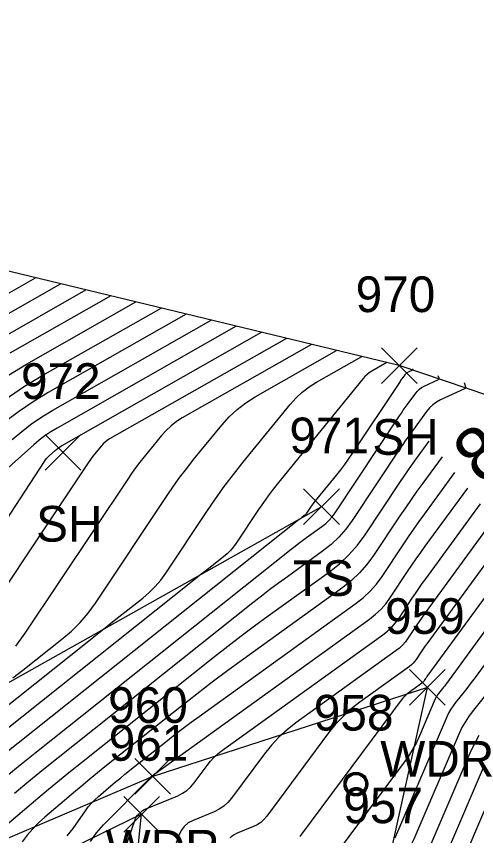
# Model space of a CAD drawing. Extents: x 1650836 to 1652450, y 332578 to 333908.
# Drawn here: x 1652020.77 to 1652046.56, y 332883.74 to 332929.66 of the extents above; entities that cross this region are included whole.
import ezdxf

# ---------------------------------------------------------------- set-up
doc = ezdxf.new("R2010")
doc.units = 0
for name, color, linetype in [('L_A', 7, 'Continuous'), ('L_I', 7, 'Continuous'), ('L_TIC', 7, 'Continuous'), ('LAWA', 7, 'Continuous'), ('LELB', 7, 'Continuous'), ('LSOGCMA', 7, 'Continuous'), ('LSOGCMA_T', 7, 'Continuous'), ('LSOGCMI', 7, 'Continuous'), ('LSOGP', 7, 'Continuous'), ('R_I', 7, 'Continuous'), ('R_TIC', 7, 'Continuous'), ('RDW', 7, 'Continuous'), ('U_I', 7, 'Continuous'), ('UWW', 7, 'Continuous')]:
    doc.layers.add(name, color=color, linetype=linetype)

msp = doc.modelspace()

# ---------------------------------------------------------------- linework, layer by layer
at = {"layer": 'L_TIC'}
for points in [[(1652041.229, 332909.088), (1652043.229, 332911.088)], [(1652043.229, 332909.088), (1652041.229, 332911.088)], [(1652022.391, 332904.221), (1652024.391, 332906.221)], [(1652024.391, 332904.221), (1652022.391, 332906.221)], [(1652036.868, 332901.175), (1652038.868, 332903.175)], [(1652038.868, 332901.175), (1652036.868, 332903.175)], [(1652042.799, 332891.048), (1652044.799, 332893.048)], [(1652044.799, 332891.048), (1652042.799, 332893.048)], [(1652027.411, 332886.059), (1652029.411, 332888.059)], [(1652029.411, 332886.059), (1652027.411, 332888.059)]]:
    msp.add_lwpolyline(points, dxfattribs=at)
at = {"layer": 'LAWA'}
msp.add_lwpolyline([(1652029.035, 332873.993), (1652029.332, 332877.691), (1652041.456, 332881.438), (1652043.799, 332892.048), (1652028.411, 332887.059), (1652010.628, 332879.467), (1652005.763, 332881.337), (1651975.403, 332896.414), (1651937.407, 332919.099), (1651902.904, 332934.281), (1651873.829, 332953.989)], dxfattribs=at)
at = {"layer": 'LELB'}
msp.add_lwpolyline([(1652037.868, 332902.175), (1652009.704, 332886.341)], dxfattribs=at)
at = {"layer": 'LSOGCMA'}
for points in [[(1651982.104, 332899.542), (1652000.106, 332897.594), (1652000.186, 332897.593), (1652000.261, 332897.606), (1652000.331, 332897.635), (1652000.398, 332897.678), (1652000.655, 332897.882), (1652000.718, 332897.933), (1652000.782, 332897.986), (1652000.844, 332898.039), (1652000.905, 332898.093), (1652015.035, 332910.743), (1652015.649, 332911.264), (1652016.288, 332911.75), (1652016.952, 332912.201), (1652017.641, 332912.618), (1652021.85, 332915.012)], [(1652035.907, 332911.616), (1652025.987, 332905.974), (1652025.861, 332905.894), (1652025.743, 332905.803), (1652025.635, 332905.703), (1652025.535, 332905.591), (1652025.155, 332905.124), (1652025.062, 332905.006), (1652024.971, 332904.886), (1652024.883, 332904.764), (1652024.798, 332904.639), (1652016.954, 332892.876)], [(1652023.627, 332883.722), (1652023.793, 332883.93), (1652023.95, 332884.145), (1652024.638, 332885.134), (1652024.8, 332885.352), (1652024.976, 332885.557), (1652025.164, 332885.751), (1652025.366, 332885.933), (1652026.199, 332886.638), (1652026.407, 332886.813), (1652026.617, 332886.987), (1652026.829, 332887.159), (1652027.041, 332887.33), (1652029.235, 332889.077), (1652029.674, 332889.422), (1652030.117, 332889.762), (1652030.564, 332890.096), (1652031.014, 332890.425), (1652039.81, 332896.764), (1652040.224, 332897.091), (1652040.604, 332897.452), (1652040.95, 332897.845), (1652041.261, 332898.272), (1652042.438, 332900.043), (1652042.734, 332900.485), (1652043.036, 332900.923), (1652043.342, 332901.357), (1652043.653, 332901.788), (1652045.34, 332904.096)], [(1652046.933, 332887.542), (1652044.985, 332882.999), (1652044.53, 332882.085), (1652043.981, 332881.242), (1652043.336, 332880.469), (1652042.596, 332879.767), (1652041.021, 332878.432)]]:
    msp.add_lwpolyline(points, dxfattribs=at)
at = {"layer": 'LSOGCMI'}
for points in [[(1652023.256, 332914.673), (1652018.565, 332912.004)], [(1652019.49, 332911.391), (1652024.662, 332914.333)], [(1652026.067, 332913.993), (1652020.414, 332910.778)], [(1652020.334, 332909.557), (1652021.338, 332910.164), (1652027.473, 332913.654)], [(1652030.284, 332912.974), (1652022.56, 332908.581), (1652021.706, 332908.065), (1652020.883, 332907.505), (1652020.092, 332906.903)], [(1652020.136, 332908.187), (1652021.18, 332908.896), (1652022.263, 332909.551), (1652028.878, 332913.314)], [(1652020.538, 332905.95), (1652021.072, 332906.403), (1652021.629, 332906.826), (1652022.207, 332907.219), (1652022.807, 332907.582), (1652031.69, 332912.635)], [(1652033.095, 332912.295), (1652023.054, 332906.583), (1652022.708, 332906.374), (1652022.374, 332906.147), (1652022.053, 332905.903), (1652021.745, 332905.642), (1652020.537, 332904.56), (1652020.245, 332904.281), (1652019.973, 332903.985), (1652019.721, 332903.671), (1652019.49, 332903.34), (1652012.737, 332892.984), (1652012.351, 332892.446), (1652011.92, 332891.948), (1652011.446, 332891.493), (1652010.928, 332891.079), (1652008.546, 332889.342), (1652008.106, 332889.06), (1652007.844, 332888.935)], [(1652007.881, 332887.532), (1652008.025, 332887.56), (1652008.577, 332887.743), (1652009.101, 332887.993), (1652009.598, 332888.312), (1652012.291, 332890.275), (1652012.877, 332890.743), (1652013.413, 332891.258), (1652013.899, 332891.82), (1652014.336, 332892.429), (1652022.35, 332904.72), (1652022.412, 332904.808), (1652022.479, 332904.892), (1652022.552, 332904.971), (1652022.63, 332905.045), (1652022.952, 332905.333), (1652023.034, 332905.403), (1652023.12, 332905.468), (1652023.208, 332905.529), (1652023.301, 332905.585), (1652034.501, 332911.956)], [(1652037.312, 332911.276), (1652030.068, 332907.156), (1652029.743, 332906.95), (1652029.441, 332906.718), (1652029.162, 332906.459), (1652028.906, 332906.172), (1652027.929, 332904.97), (1652027.688, 332904.667), (1652027.455, 332904.358), (1652027.229, 332904.044), (1652027.011, 332903.725), (1652021.255, 332895.094), (1652020.72, 332894.356)], [(1652020.581, 332892.58), (1652021.13, 332893.013), (1652023.325, 332894.745), (1652023.854, 332895.197), (1652024.342, 332895.686), (1652024.79, 332896.212), (1652025.198, 332896.775), (1652029.223, 332902.81), (1652029.575, 332903.325), (1652029.939, 332903.831), (1652030.315, 332904.328), (1652030.703, 332904.816), (1652032.277, 332906.753), (1652032.689, 332907.215), (1652033.138, 332907.633), (1652033.625, 332908.007), (1652034.148, 332908.337), (1652038.718, 332910.937)], [(1652015.744, 332887.432), (1652024.83, 332894.668), (1652025.207, 332894.968), (1652025.584, 332895.267), (1652025.961, 332895.566), (1652026.339, 332895.865), (1652027.851, 332897.058), (1652028.215, 332897.369), (1652028.552, 332897.705), (1652028.86, 332898.068), (1652029.141, 332898.455), (1652031.445, 332901.909), (1652031.926, 332902.612), (1652032.423, 332903.304), (1652032.936, 332903.983), (1652033.466, 332904.65), (1652036.118, 332907.912), (1652036.44, 332908.273), (1652036.791, 332908.6), (1652037.171, 332908.892), (1652037.581, 332909.151), (1652040.124, 332910.597)], [(1652041.529, 332910.258), (1652040.684, 332909.777), (1652040.548, 332909.691), (1652040.422, 332909.594), (1652040.305, 332909.485), (1652040.198, 332909.365), (1652035.455, 332903.532), (1652035.165, 332903.166), (1652034.883, 332902.794), (1652034.611, 332902.415), (1652034.347, 332902.029), (1652033.085, 332900.136), (1652032.93, 332899.923), (1652032.761, 332899.725), (1652032.577, 332899.54), (1652032.377, 332899.37), (1652031.549, 332898.716), (1652031.341, 332898.552), (1652031.135, 332898.389), (1652030.928, 332898.225), (1652030.721, 332898.06), (1652017.856, 332887.814)], [(1652042.959, 332909.899), (1652042.974, 332909.851), (1652042.975, 332909.843), (1652042.974, 332909.837), (1652042.97, 332909.832), (1652042.964, 332909.828), (1652042.693, 332909.702), (1652042.647, 332909.677), (1652042.606, 332909.647), (1652042.569, 332909.612), (1652042.536, 332909.572), (1652042.376, 332909.354), (1652042.339, 332909.303), (1652042.303, 332909.252), (1652042.267, 332909.2), (1652042.232, 332909.148), (1652039.567, 332905.135), (1652039.363, 332904.836), (1652039.153, 332904.542), (1652038.935, 332904.254), (1652038.71, 332903.97), (1652037.444, 332902.413), (1652037.393, 332902.349), (1652037.344, 332902.283), (1652037.296, 332902.217), (1652037.249, 332902.149), (1652037.028, 332901.817), (1652037.001, 332901.779), (1652036.971, 332901.745), (1652036.939, 332901.712), (1652036.903, 332901.682), (1652036.758, 332901.567), (1652036.722, 332901.539), (1652036.685, 332901.51), (1652036.649, 332901.481), (1652036.613, 332901.452), (1652019.967, 332888.196)], [(1652019.767, 332886.712), (1652020.786, 332887.542), (1652021.811, 332888.364), (1652036.173, 332899.802), (1652036.384, 332899.968), (1652036.596, 332900.131), (1652036.81, 332900.291), (1652037.026, 332900.449), (1652037.895, 332901.075), (1652038.103, 332901.239), (1652038.294, 332901.421), (1652038.468, 332901.619), (1652038.625, 332901.833), (1652042.239, 332907.276), (1652042.344, 332907.431), (1652042.45, 332907.586), (1652042.558, 332907.739), (1652042.668, 332907.891), (1652043.146, 332908.545), (1652043.245, 332908.664), (1652043.356, 332908.769), (1652043.48, 332908.858), (1652043.617, 332908.932), (1652044.426, 332909.309), (1652044.445, 332909.321), (1652044.457, 332909.337), (1652044.461, 332909.356), (1652044.457, 332909.378), (1652044.413, 332909.522)], [(1652045.868, 332909.145), (1652045.941, 332908.905), (1652045.947, 332908.868), (1652045.94, 332908.836), (1652045.921, 332908.81), (1652045.889, 332908.79), (1652044.54, 332908.161), (1652044.313, 332908.038), (1652044.107, 332907.89), (1652043.921, 332907.716), (1652043.756, 332907.517), (1652042.96, 332906.428), (1652042.777, 332906.174), (1652042.597, 332905.919), (1652042.42, 332905.662), (1652042.246, 332905.403), (1652039.587, 332901.399), (1652039.231, 332900.912), (1652038.836, 332900.462), (1652038.402, 332900.051), (1652037.929, 332899.677), (1652035.957, 332898.256), (1652035.466, 332897.897), (1652034.98, 332897.533), (1652034.498, 332897.164), (1652034.021, 332896.788), (1652023.118, 332888.105), (1652022.297, 332887.446), (1652021.48, 332886.781), (1652020.668, 332886.109)], [(1652018.845, 332883.187), (1652021.973, 332885.834), (1652022.581, 332886.344), (1652023.192, 332886.849), (1652023.807, 332887.35), (1652024.426, 332887.847), (1652031.868, 332893.773), (1652032.612, 332894.359), (1652033.364, 332894.936), (1652034.123, 332895.504), (1652034.888, 332896.062), (1652038.315, 332898.532), (1652038.884, 332898.982), (1652039.406, 332899.477), (1652039.882, 332900.018), (1652040.31, 332900.605), (1652042.253, 332903.53), (1652042.497, 332903.893), (1652042.744, 332904.253), (1652042.996, 332904.61), (1652043.252, 332904.964), (1652043.901, 332905.852)], [(1652044.62, 332904.974), (1652043.544, 332903.501), (1652043.215, 332903.046), (1652042.892, 332902.587), (1652042.573, 332902.124), (1652042.26, 332901.658), (1652040.785, 332899.438), (1652040.416, 332898.932), (1652040.005, 332898.465), (1652039.554, 332898.037), (1652039.062, 332897.648), (1652033.5, 332893.639), (1652032.619, 332892.996), (1652031.745, 332892.342), (1652030.88, 332891.678), (1652030.022, 332891.004), (1652025.734, 332887.588), (1652025.318, 332887.255), (1652024.905, 332886.918), (1652024.494, 332886.578), (1652024.086, 332886.236), (1652022.367, 332884.782), (1652022.017, 332884.466), (1652021.69, 332884.129), (1652021.385, 332883.771), (1652021.104, 332883.393)], [(1652024.919, 332883.414), (1652025.257, 332883.895), (1652025.653, 332884.34), (1652028.178, 332886.889), (1652028.186, 332886.899), (1652028.195, 332886.908), (1652028.203, 332886.918), (1652028.21, 332886.929), (1652028.241, 332886.972), (1652028.248, 332886.982), (1652028.256, 332886.991), (1652028.264, 332887), (1652028.273, 332887.008), (1652028.311, 332887.04), (1652028.32, 332887.048), (1652028.33, 332887.056), (1652028.34, 332887.064), (1652028.349, 332887.071), (1652028.448, 332887.15), (1652028.468, 332887.166), (1652028.488, 332887.181), (1652028.508, 332887.196), (1652028.529, 332887.211), (1652040.558, 332895.88), (1652040.894, 332896.146), (1652041.203, 332896.439), (1652041.484, 332896.759), (1652041.737, 332897.105), (1652042.693, 332898.545), (1652042.934, 332898.903), (1652043.179, 332899.259), (1652043.428, 332899.612), (1652043.681, 332899.962), (1652046.059, 332903.218)], [(1652025.199, 332878.188), (1652027.422, 332884.647), (1652027.448, 332884.711), (1652027.481, 332884.771), (1652027.52, 332884.827), (1652027.566, 332884.879), (1652027.763, 332885.078), (1652027.815, 332885.125), (1652027.87, 332885.166), (1652027.929, 332885.201), (1652027.991, 332885.23), (1652029.814, 332885.98), (1652030.083, 332886.112), (1652030.327, 332886.276), (1652030.546, 332886.472), (1652030.74, 332886.701), (1652031.467, 332887.679), (1652031.656, 332887.915), (1652031.863, 332888.134), (1652032.085, 332888.337), (1652032.324, 332888.524), (1652041.305, 332894.996), (1652041.564, 332895.201), (1652041.802, 332895.426), (1652042.018, 332895.672), (1652042.212, 332895.939), (1652042.948, 332897.046), (1652043.133, 332897.322), (1652043.322, 332897.596), (1652043.513, 332897.867), (1652043.708, 332898.137), (1652046.779, 332902.34)], [(1652047.418, 332901.351), (1652043.735, 332896.311), (1652043.599, 332896.123), (1652043.465, 332895.932), (1652043.333, 332895.741), (1652043.203, 332895.548), (1652042.688, 332894.772), (1652042.552, 332894.585), (1652042.401, 332894.413), (1652042.234, 332894.255), (1652042.053, 332894.112), (1652036.431, 332890.061), (1652035.942, 332889.679), (1652035.486, 332889.263), (1652035.063, 332888.813), (1652034.674, 332888.329), (1652032.822, 332885.835), (1652032.618, 332885.596), (1652032.389, 332885.39), (1652032.133, 332885.218), (1652031.851, 332885.08), (1652030.67, 332884.594), (1652030.398, 332884.45), (1652030.174, 332884.261), (1652029.997, 332884.028), (1652029.867, 332883.749), (1652029.066, 332881.486)], [(1652048.028, 332900.324), (1652043.763, 332894.486), (1652043.685, 332894.378), (1652043.608, 332894.269), (1652043.532, 332894.159), (1652043.458, 332894.049), (1652043.164, 332893.606), (1652043.086, 332893.499), (1652042.999, 332893.4), (1652042.904, 332893.31), (1652042.801, 332893.228), (1652040.009, 332891.217), (1652039.525, 332890.839), (1652039.074, 332890.427), (1652038.655, 332889.982), (1652038.27, 332889.503), (1652034.799, 332884.828), (1652034.642, 332884.644), (1652034.465, 332884.485), (1652034.267, 332884.352), (1652034.05, 332884.246), (1652033.139, 332883.871), (1652032.93, 332883.76), (1652032.757, 332883.615)], [(1652036.665, 332883.692), (1652036.776, 332883.822), (1652042.411, 332891.409), (1652042.507, 332891.529), (1652042.612, 332891.641), (1652042.726, 332891.744), (1652042.847, 332891.839), (1652043.548, 332892.344), (1652043.574, 332892.365), (1652043.598, 332892.388), (1652043.62, 332892.412), (1652043.639, 332892.439), (1652043.713, 332892.55), (1652043.732, 332892.578), (1652043.751, 332892.606), (1652043.77, 332892.633), (1652043.79, 332892.66), (1652048.638, 332899.296)], [(1652049.249, 332898.269), (1652044.865, 332892.269), (1652044.812, 332892.198), (1652044.759, 332892.127), (1652044.704, 332892.056), (1652044.649, 332891.986), (1652044.427, 332891.708), (1652044.374, 332891.637), (1652044.326, 332891.563), (1652044.283, 332891.486), (1652044.246, 332891.406), (1652043.353, 332889.326), (1652043.183, 332888.958), (1652042.992, 332888.602), (1652042.78, 332888.257), (1652042.547, 332887.925), (1652038.752, 332882.815)], [(1652050.104, 332897.577), (1652046.469, 332892.602), (1652046.337, 332892.423), (1652046.203, 332892.245), (1652046.066, 332892.069), (1652045.928, 332891.894), (1652045.371, 332891.198), (1652045.239, 332891.02), (1652045.119, 332890.834), (1652045.012, 332890.641), (1652044.917, 332890.44), (1652042.075, 332883.813), (1652041.971, 332883.589)], [(1652047.207, 332891.801), (1652046.316, 332890.687), (1652046.104, 332890.402), (1652045.912, 332890.105), (1652045.74, 332889.795), (1652045.589, 332889.474), (1652043.049, 332883.55), (1652042.523, 332882.494), (1652041.888, 332881.52), (1652041.143, 332880.626), (1652040.288, 332879.814), (1652038.89, 332878.63)], [(1652039.955, 332878.531), (1652041.442, 332879.791), (1652042.24, 332880.548), (1652042.934, 332881.381), (1652043.527, 332882.29), (1652044.017, 332883.274), (1652046.261, 332888.508), (1652046.469, 332888.95), (1652046.705, 332889.376)], [(1652047.605, 332886.576), (1652045.953, 332882.723), (1652045.534, 332881.881), (1652045.027, 332881.103), (1652044.433, 332880.391), (1652043.751, 332879.743), (1652041.813, 332878.101)]]:
    msp.add_lwpolyline(points, dxfattribs=at)
at = {"layer": 'LSOGP'}
msp.add_lwpolyline([(1652322.392, 332778.396), (1652286.244, 332816.269), (1652278.684, 332833.467), (1652279.741, 332838.109), (1652281.376, 332840.252), (1652284.715, 332848.326), (1652266.979, 332860.629), (1652252.966, 332867.026), (1652234.442, 332886.186), (1652219.944, 332895.981), (1652193.017, 332893.494), (1652163.094, 332891.822), (1652141.158, 332895.272), (1652101.604, 332894.697), (1652074.965, 332899.016), (1652042.229, 332910.088), (1652009.557, 332917.982), (1651992.258, 332920.35), (1651945.495, 332936.417)], dxfattribs=at)
at = {"layer": 'R_TIC'}
for points in [[(1652026.792, 332883.937), (1652028.792, 332885.937)], [(1652028.792, 332883.937), (1652026.792, 332885.937)]]:
    msp.add_lwpolyline(points, dxfattribs=at)
at = {"layer": 'RDW'}
msp.add_lwpolyline([(1652007.153, 332861.07), (1652010.739, 332865.279), (1652018.452, 332871.644), (1652026.901, 332876.261), (1652027.792, 332884.937), (1652012.255, 332877.382), (1652007.989, 332873.849), (1651997.288, 332866.232)], dxfattribs=at)
at = {"layer": 'UWW'}
for radius in [0.667, 0.625, 0.583, 0.542]:
    msp.add_circle((1652039.799, 332886.631), radius, dxfattribs=at)

# ---------------------------------------------------------------- texts
at = {"layer": 'L_A'}
for s, p in [('SH', (1652040.717, 332905.088)), ('SH', (1652021.879, 332900.221)), ('TS', (1652036.277, 332897.175)), ('WDR', (1652041.161, 332887.048)), ('WDR', (1652025.773, 332882.059))]:
    msp.add_text(s, height=2, dxfattribs=at).set_placement(p)
at = {"layer": 'L_I'}
for s, p in [('970', (1652039.78, 332913.088)), ('972', (1652021.029, 332908.221)), ('971', (1652036.072, 332905.175)), ('959', (1652041.429, 332895.048)), ('960', (1652025.915, 332890.059)), ('957', (1652039.094, 332884.438))]:
    msp.add_text(s, height=2, dxfattribs=at).set_placement(p)
at = {"layer": 'LSOGCMA_T'}
msp.add_text('815', height=3, rotation=39.3343, dxfattribs=at).set_placement((1652046.855, 332903.309))
at = {"layer": 'R_I'}
msp.add_text('961', height=2, dxfattribs=at).set_placement((1652025.949, 332887.937))
at = {"layer": 'U_I'}
msp.add_text('958', height=2, dxfattribs=at).set_placement((1652037.437, 332889.631))

doc.saveas('drawing.dxf')
